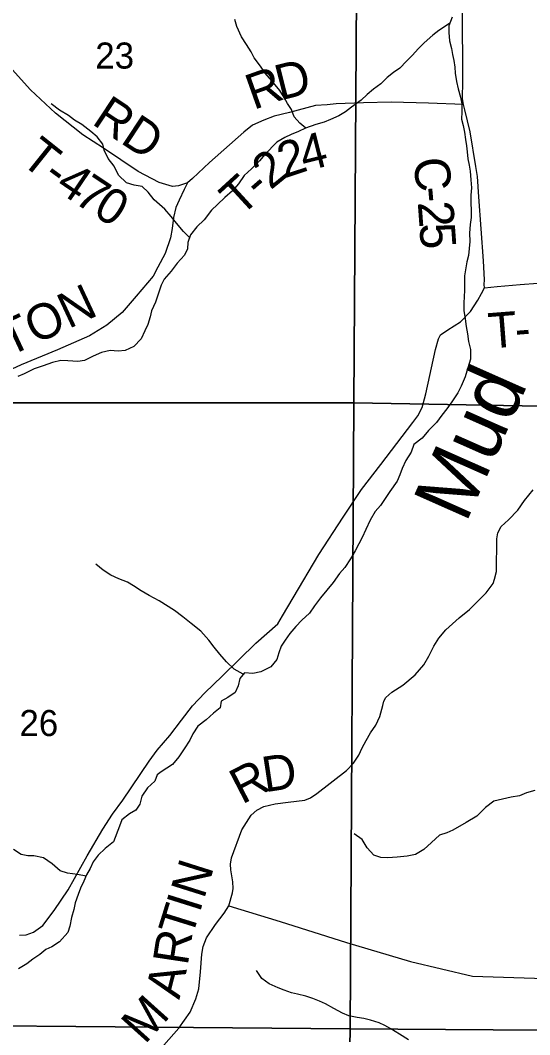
# Model space of a CAD drawing. Extents: x 2043100 to 2470832, y 443715 to 810583.
# Drawn here: x 2283141 to 2287455, y 675442 to 684041 of the extents above; entities that cross this region are included whole.
import ezdxf

# ---------------------------------------------------------------- set-up
doc = ezdxf.new("R2010")
doc.units = 0
for name, color, linetype in [('GM_X_County_Road', 7, 'Continuous'), ('GM_X_County_Road_Text', 7, 'Continuous'), ('GM_X_Minor_River', 7, 'Continuous'), ('GM_X_Minor_River_Text', 7, 'Continuous'), ('GM_X_Section', 7, 'Continuous'), ('GM_X_Section_Text', 7, 'Continuous'), ('GM_X_Township_Road', 7, 'Continuous'), ('GM_X_Township_Road_Text', 7, 'Continuous'), ('GM_X_Township_ROW', 7, 'Continuous')]:
    doc.layers.add(name, color=color, linetype=linetype)

msp = doc.modelspace()

# ---------------------------------------------------------------- linework, layer by layer
at = {"layer": 'GM_X_County_Road'}
for points in [[(2287071.6, 681774.3), (2287069.3, 681800.3), (2287071, 681840.4), (2287063.5, 682000.7), (2287024.6, 682543.7), (2287013, 682717.9), (2286998.2, 682802), (2286951.5, 683094.3), (2286905.8, 683282.3), (2286895.3, 683328.3), (2286886.9, 683374.3), (2286889.6, 683526.7), (2286886, 684146.1)], [(2283133.6, 676286.8), (2283189.7, 676287.2), (2283251.6, 676311.7), (2283331.3, 676368.3), (2283426.5, 676493.2), (2283545.5, 676670.4), (2283707.6, 676958.1), (2283840.2, 677185.4), (2283921.4, 677310.2), (2284008.7, 677431), (2284232.6, 677761.2), (2284300.1, 677853.9), (2284406.1, 677978.1), (2284505.1, 678109.3), (2284600.1, 678228.4), (2284703.3, 678339.6), (2284850.2, 678481.2), (2285136.1, 678760.3), (2285320.8, 678924.3), (2285362.3, 678992.9), (2285451, 679146), (2285670, 679512.8), (2285875.4, 679829.3), (2286029.5, 680063.2), (2286193.9, 680275.1), (2286465, 680630.3), (2286506.6, 680686.8), (2286544, 680757.3), (2286575, 680873.9), (2286657.7, 681251.5), (2286682.9, 681341.9), (2286700.7, 681374.1), (2286762.4, 681416.8), (2286868.3, 681485.2), (2286953, 681572), (2287014.4, 681669.6), (2287048, 681726), (2287071.6, 681774.3)]]:
    msp.add_lwpolyline(points, dxfattribs=at)
at = {"layer": 'GM_X_Minor_River'}
for points in [[(2286777, 684013.3), (2286685.8, 683955.8), (2286634.1, 683915.5), (2286562.5, 683849), (2286510.8, 683798.6), (2286463.2, 683746.2), (2286411.5, 683693.8), (2286355.9, 683635.4), (2286302.2, 683599.1), (2286246.5, 683554.7), (2286194.8, 683502.3), (2286131.1, 683457.9), (2286079.4, 683411.5), (2286027.7, 683363.1), (2285946.1, 683304.6), (2285894.4, 683266.2), (2285838.7, 683231.8), (2285768.9, 683199.4), (2285715.1, 683177), (2285643.2, 683158.6), (2285557.5, 683126), (2285497.7, 683097.6), (2285433.9, 683073.2), (2285380.1, 683046.8), (2285314.3, 683008.4), (2285211, 682903.7), (2285165.4, 682849.3), (2285099.8, 682780.8), (2285036.2, 682726.4), (2284988.6, 682656), (2284937, 682595.6), (2284873.4, 682539.1), (2284811.8, 682480.7), (2284760.1, 682430.3), (2284698.6, 682349.8), (2284637, 682289.4), (2284583.5, 682223), (2284559.8, 682158.7), (2284556.2, 682102.7), (2284532.5, 682050.4), (2284468.9, 681982), (2284419.4, 681913.6), (2284359.8, 681845.1), (2284334.1, 681794.9), (2284285.2, 681650.7)], [(2285560.3, 683127.1), (2285507.3, 683167.8), (2285461, 683221.6), (2285436.7, 683283.5), (2285404.4, 683335.4), (2285374.1, 683387.3), (2285339.8, 683447.2), (2285271.4, 683528.9), (2285215, 683592.7), (2285174.7, 683652.5), (2285120.4, 683722.3), (2285096.1, 683774.2), (2285055.8, 683836.1), (2285015.4, 683901.9), (2284974.9, 683989.8), (2284958.6, 684047.8)], [(2286799.1, 684068.7), (2286769.5, 683994.4), (2286769.8, 683938.3), (2286774.3, 683866.2), (2286792.6, 683802.2), (2286800.9, 683750.2), (2286813.2, 683700.2), (2286819.5, 683644.2), (2286823.8, 683592.1), (2286836.2, 683522.1), (2286848.5, 683460.1), (2286868.9, 683390.1), (2286879.2, 683334.1), (2286879.6, 683266), (2286878, 683203.9), (2286890.3, 683149.9), (2286902.6, 683091.9), (2286911, 683031.8), (2286919.3, 682975.8), (2286925.6, 682925.8), (2286931.9, 682867.7), (2286942.2, 682811.7), (2286950.5, 682761.7), (2286956.9, 682687.6), (2286961.3, 682621.5), (2286955.7, 682559.4), (2286956.1, 682493.3), (2286958.4, 682427.2), (2286958.8, 682369.2), (2286951.1, 682309), (2286945.6, 682236.9), (2286948, 682164.8), (2286942.3, 682106.7), (2286936.7, 682046.6), (2286923, 681992.4), (2286911.4, 681926.2), (2286903.7, 681876.1), (2286902.1, 681804), (2286902.4, 681753.9), (2286900.7, 681697.8), (2286897, 681645.8), (2286897.4, 681581.7), (2286907.8, 681511.6), (2286916.2, 681445.6), (2286928.5, 681383.6), (2286936.9, 681317.5), (2286953.3, 681249.5), (2286953.7, 681169.4), (2286932.2, 681095.2), (2286908.6, 681018.9), (2286873.1, 680940.6), (2286847.5, 680882.4), (2286795.9, 680807.9), (2286752.3, 680747.6), (2286710.7, 680693.3), (2286665.1, 680630.9), (2286597.5, 680562.4), (2286543.9, 680498), (2286472.3, 680445.5), (2286450.7, 680381.3), (2286405.1, 680308.9), (2286373.6, 680240.6), (2286353.9, 680188.4), (2286332.2, 680134.2), (2286270.8, 680045.8), (2286235.1, 679995.5), (2286191.5, 679929.1), (2286145.8, 679876.8), (2286104.3, 679804.4), (2286066.8, 679724.1), (2286037.2, 679657.8), (2286007.5, 679603.6), (2285975.9, 679543.3), (2285936.3, 679475), (2285888.8, 679402.6), (2285845.1, 679352.2), (2285789.6, 679275.8), (2285738, 679211.4), (2285684.4, 679145), (2285632.9, 679078.6), (2285589.3, 679014.2), (2285523.7, 678955.8), (2285474, 678901.4), (2285424.4, 678843), (2285384.7, 678786.7), (2285351.1, 678734.4), (2285329.4, 678678.2)], [(2284274.4, 682519.6), (2284222.6, 682585.1), (2284172.1, 682632.7), (2284104, 682644), (2284039.8, 682663.4), (2283973.2, 682728.8), (2283936.4, 682804.5), (2283883.8, 682870), (2283851.1, 682939.8), (2283840.5, 682991.7), (2283791.9, 683053.3), (2283737.5, 683098.8), (2283662.9, 683158.1), (2283600.5, 683195.5), (2283548.2, 683235), (2283471.7, 683278.3), (2283401.2, 683331.6)], [(2284574.4, 682198.4), (2284523.3, 682250.7), (2284463, 682322.4), (2284418.7, 682378.2), (2284364.4, 682440), (2284274.4, 682519.6)], [(2284285.2, 681650.7), (2284250.8, 681578.3), (2284239.4, 681526.1), (2284220, 681461.9), (2284196.6, 681407.6), (2284165.3, 681341.2), (2284102, 681276.5), (2284028.4, 681241.7), (2283968.4, 681237.1), (2283902.4, 681240.4), (2283828.6, 681225.7), (2283758.9, 681192.9), (2283683.3, 681158.1), (2283627.4, 681149.6), (2283543.4, 681154.7), (2283483.4, 681158.1), (2283413.6, 681141.4), (2283335.9, 681112.6), (2283258.2, 681085.8), (2283172.7, 681044.8), (2283120.9, 681020.3)], [(2284316.6, 679120.3), (2284231.5, 679165.5), (2284165.1, 679204.9), (2284098.7, 679248.2), (2284048.4, 679277.8), (2283974.1, 679307.1), (2283907.8, 679338.4), (2283843.4, 679379.8), (2283780.9, 679429.2)], [(2285028.4, 678497.3), (2284952.5, 678539.8), (2284886.2, 678601.5), (2284831.9, 678667.3), (2284783.6, 678727.1), (2284737.2, 678784.9), (2284668.9, 678862.6), (2284588.5, 678926.2), (2284516.3, 678983.9), (2284448, 679037.6), (2284316.6, 679120.3)], [(2285329.4, 678678.2), (2285313.7, 678622), (2285262.2, 678559.7), (2285178.5, 678517.1), (2285110.6, 678504.7), (2285038.6, 678510.3), (2284998.9, 678460), (2284985.3, 678399.8), (2284959.6, 678343.6), (2284897.9, 678299.1), (2284842.2, 678268.8), (2284834.5, 678212.6), (2284776.8, 678168.2), (2284715.2, 678111.8), (2284645.5, 678057.3), (2284602, 677991), (2284576.3, 677938.7), (2284528.7, 677866.3), (2284483.2, 677796), (2284429.6, 677731.6), (2284334.6, 677668.9)], [(2284334.6, 677668.9), (2284299, 677644.5), (2284281.5, 677592.3), (2284218.2, 677533.6), (2284168.9, 677465), (2284153.6, 677396.8), (2284118.1, 677346.4), (2284064.5, 677313.8), (2284001, 677263.1), (2283979.6, 677208.8), (2283928.9, 677076.2), (2283859.5, 677021.4), (2283800.1, 676962.8), (2283758.7, 676906.3), (2283731.3, 676849.9), (2283701.9, 676795.6), (2283678.4, 676743.3), (2283651.1, 676682.9), (2283629.6, 676630.7), (2283606.3, 676560.4), (2283592.9, 676504.2), (2283575.6, 676435.9), (2283560.4, 676361.7), (2283542.9, 676307.4), (2283473.8, 676228.7), (2283408.2, 676185.9), (2283356.4, 676165.4), (2283304.9, 676122.8), (2283247.3, 676082.2), (2283195.8, 676041.6), (2283126.2, 676000.9)], [(2287498.5, 677511.3), (2287428.7, 677490.9), (2287368.9, 677466.5), (2287297, 677454), (2287223.1, 677439.6), (2287151.3, 677421.1), (2287079.7, 677368.6), (2287006.1, 677294.1), (2286916.5, 677241.5), (2286805, 677176.7), (2286753.2, 677152.4), (2286691.3, 677132), (2286623.7, 677071.5), (2286558.1, 677013), (2286486.4, 676970.6), (2286416.6, 676956.1), (2286332.7, 676945.6), (2286252.8, 676941.2), (2286194.8, 676942.8)], [(2286194.8, 676942.8), (2286134.7, 676964.5), (2286078.4, 677026.2), (2286036, 677096.1), (2285967.8, 677143.8)], [(2283698, 676786.9), (2283623.9, 676800.8), (2283539.8, 676812), (2283479.6, 676831.4), (2283411, 676890.7), (2283336.5, 676942), (2283256.4, 676959.3), (2283204.4, 676958.7), (2283148.3, 676970.2), (2283081.9, 677011.5)], [(2286429.6, 675397.9), (2286351.4, 675445.5), (2286279.2, 675491.2), (2286229, 675518.9), (2286178.9, 675542.7), (2286106.9, 675566.3), (2286050.8, 675580), (2285992.8, 675587.7), (2285922.8, 675601.2), (2285868.7, 675625), (2285796.5, 675664.6), (2285726.3, 675704.2), (2285674.3, 675726), (2285618.2, 675749.7), (2285558.1, 675767.3), (2285488.1, 675784.9), (2285438, 675796.7), (2285375.9, 675820.3), (2285325.9, 675838.1), (2285249.7, 675873.7), (2285187.5, 675919.4), (2285141.2, 675987.2)]]:
    msp.add_lwpolyline(points, dxfattribs=at)
at = {"layer": 'GM_X_Section'}
for points in [[(2280735.8, 686074.1), (2285999.1, 685990.1), (2285965.2, 680797), (2280691.6, 680798.9)], [(2285999.1, 685990.1), (2291224.3, 685932.8), (2291199.6, 683225), (2291196.8, 680705.8), (2285965.2, 680797)], [(2280691.6, 680798.9), (2285965.2, 680797), (2285935, 675492.2), (2280621.4, 675535.8)], [(2285965.2, 680797), (2291196.8, 680705.8), (2291189.1, 677184.1), (2291175.8, 675455.1), (2285935, 675492.2)], [(2280621.4, 675535.8), (2285935, 675492.2), (2285836.8, 670182.6), (2280537.8, 670232.5)], [(2285935, 675492.2), (2291175.8, 675455.1), (2291157.4, 671835.3), (2291147.7, 670142.4), (2285836.8, 670182.6)]]:
    msp.add_lwpolyline(points, close=True, dxfattribs=at)
at = {"layer": 'GM_X_Township_Road'}
for points in [[(2284558.2, 682664.2), (2284480.3, 682637.5), (2284430.3, 682633), (2284317.8, 682666.1), (2284138.6, 682757.9), (2283844.7, 682958.2), (2283671.7, 683071.2), (2283438, 683253.9), (2283226.3, 683452.8), (2283072.8, 683624), (2282959.1, 683839.6), (2282908.3, 683937.5), (2282881.8, 684001.4), (2282889.4, 684061.6), (2282916.6, 684184), (2282921.4, 684344.3), (2282920.5, 684466.5), (2282849.9, 684817.9), (2282828.4, 685037)], [(2286895.3, 683328.3), (2286598.8, 683339.7), (2286280.3, 683346.9), (2286046.1, 683340.9), (2285815.8, 683332.8), (2285739.8, 683324.1), (2285641.8, 683317.3), (2285422, 683259.2), (2285290.1, 683228), (2285204.3, 683195.1), (2285108.5, 683152.2), (2285032.9, 683093.4), (2284742.9, 682836.2), (2284597.9, 682700.7), (2284558.2, 682664.2), (2284528.7, 682605.8), (2284485.4, 682517.2), (2284457.9, 682452.8), (2284438.6, 682370.5), (2284427.5, 682276.2), (2284414.2, 682197.9), (2284367.3, 682065.2), (2284306.3, 681948.4), (2284265.2, 681871.1), (2284122.2, 681703.8), (2284003, 681564.7), (2283873.6, 681455.6), (2283728, 681366.4), (2283456.5, 681246.3), (2283146.9, 681119.9), (2282731.7, 680928.6)], [(2287071.6, 681774.3), (2287179.6, 681785.3), (2287373.7, 681801), (2287673.9, 681823.7), (2287816, 681835), (2287852, 681845.3), (2287873.8, 681863.6), (2287893.6, 681893.8), (2287895.2, 681933.9), (2287904.1, 682056.3), (2287918.6, 682234.8), (2287937.7, 682335.2), (2287961.1, 682399.6), (2287978.9, 682423.8), (2288004.8, 682438), (2288024.8, 682440.2), (2288024.7, 682452.2), (2288032.3, 682500.4), (2288044, 682534.6), (2288048.3, 682543.7)], [(2284356.1, 675353.6), (2284484.5, 675497.1), (2284579.5, 675632.2), (2284628.5, 675744.9), (2284653.8, 675831.3), (2284666.5, 675973.8), (2284677.2, 676124.2), (2284688.6, 676190.5), (2284718, 676262.9), (2284793.1, 676375.8), (2284866.3, 676470.7), (2284907.8, 676533.2), (2284938.8, 676643.7), (2284942.5, 676681.8), (2284940, 676737.9), (2284925.1, 676838), (2284920.6, 676886.1), (2284930.1, 676942.3), (2285016.1, 677177.6), (2285095.1, 677302.6), (2285142.8, 677345.1), (2285204.6, 677375.8), (2285300.5, 677398.6), (2285408.6, 677411.6), (2285550.6, 677430.9), (2285598.5, 677449.4), (2285652.2, 677486), (2285902.8, 677682.6), (2285962.3, 677743.3), (2286007.8, 677811.8), (2286037.3, 677872.2), (2286068.7, 677936.7), (2286106.2, 678001.1), (2286151.7, 678065.7), (2286185.1, 678138.1), (2286210.2, 678232.6), (2286219.9, 678268.8), (2286237.7, 678299), (2286287.3, 678345.5), (2286380.9, 678404.5), (2286484.3, 678491.6), (2286559.6, 678576.5), (2286601, 678651), (2286642.3, 678735.5), (2286685.7, 678804.1), (2286745.2, 678874.8), (2286858.4, 678976), (2286945.9, 679044.9), (2287084.8, 679188.5), (2287144.2, 679267.2), (2287157.9, 679303.4), (2287173.3, 679369.7), (2287176.8, 679644.3), (2287184.4, 679696.5), (2287212, 679748.9), (2287275.5, 679807.6), (2287354.9, 679888.5), (2287410.2, 679971.1), (2287485.5, 680062)]]:
    msp.add_lwpolyline(points, dxfattribs=at)
at = {"layer": 'GM_X_Township_ROW'}
msp.add_lwpolyline([(2284907.8, 676533.2), (2285341.5, 676402.7), (2285903.9, 676223.3), (2286444.1, 676063.6), (2286969.9, 675938), (2287670.6, 675916.1)], dxfattribs=at)

# ---------------------------------------------------------------- texts
at = {"layer": 'GM_X_County_Road_Text'}
for s, rotation, p in [('C', 276.74838, (2286467.2, 682862.9)), ('-', 274.90044, (2286495.9, 682620.7)), ('2', 274.20873, (2286506.3, 682498.9)), ('5', 274.00516, (2286519.9, 682314.9))]:
    msp.add_text(s, height=300, rotation=rotation, dxfattribs=at).set_placement(p)
at = {"layer": 'GM_X_Minor_River_Text'}
msp.add_text('Mud', height=499.91, rotation=66.06677, dxfattribs=at).set_placement((2286913.5, 679769))
at = {"layer": 'GM_X_Section_Text'}
for s, p in [('23', (2283775.8, 683631.8)), ('26', (2283133.4, 677973.4))]:
    msp.add_text(s, height=220.83, rotation=0.00001, dxfattribs=at).set_placement(p)
at = {"layer": 'GM_X_Township_Road_Text'}
for s, rotation, p in [('D', 14.16877, (2285341.6, 683360)), ('R', 19.51126, (2285116.4, 683279.9)), ('RD', 326.58379, (2283737.5, 683166.5)), ('T', 321.37701, (2283131.2, 682838.2)), ('4', 14.15236, (2285547.8, 682757)), ('2', 18.25557, (2285377.8, 682700.7)), ('2', 39.21325, (2285259.9, 682597.7)), ('-', 323.77811, (2283317.4, 682689.8)), ('4', 325.8674, (2283426.5, 682610.1)), ('7', 326.47161, (2283582.3, 682504.5)), ('T', 42.55072, (2285005.4, 682367.8)), ('0', 328.16229, (2283744.5, 682397.2)), ('-', 41.23292, (2285169.4, 682518.3)), ('BRITTON', 25.03758, (2282216.6, 680800.1)), ('T', 4.44439, (2287114.3, 681258.2)), ('-', 4.49838, (2287338.4, 681275.6)), ('D', 8.65505, (2285212.3, 677496.3)), ('R', 27.33828, (2285017.9, 677391.1)), ('N', 72.44974, (2284696.1, 676585.1)), ('I', 72.47599, (2284659, 676467.7)), ('T', 72.73468, (2284592.5, 676253.7)), ('R', 81.40363, (2284558.4, 676021.8)), ('A', 75.74795, (2284487, 675734.2)), ('M', 48.00049, (2284195.1, 675353.7))]:
    msp.add_text(s, height=300, rotation=rotation, dxfattribs=at).set_placement(p)

doc.saveas('drawing.dxf')
